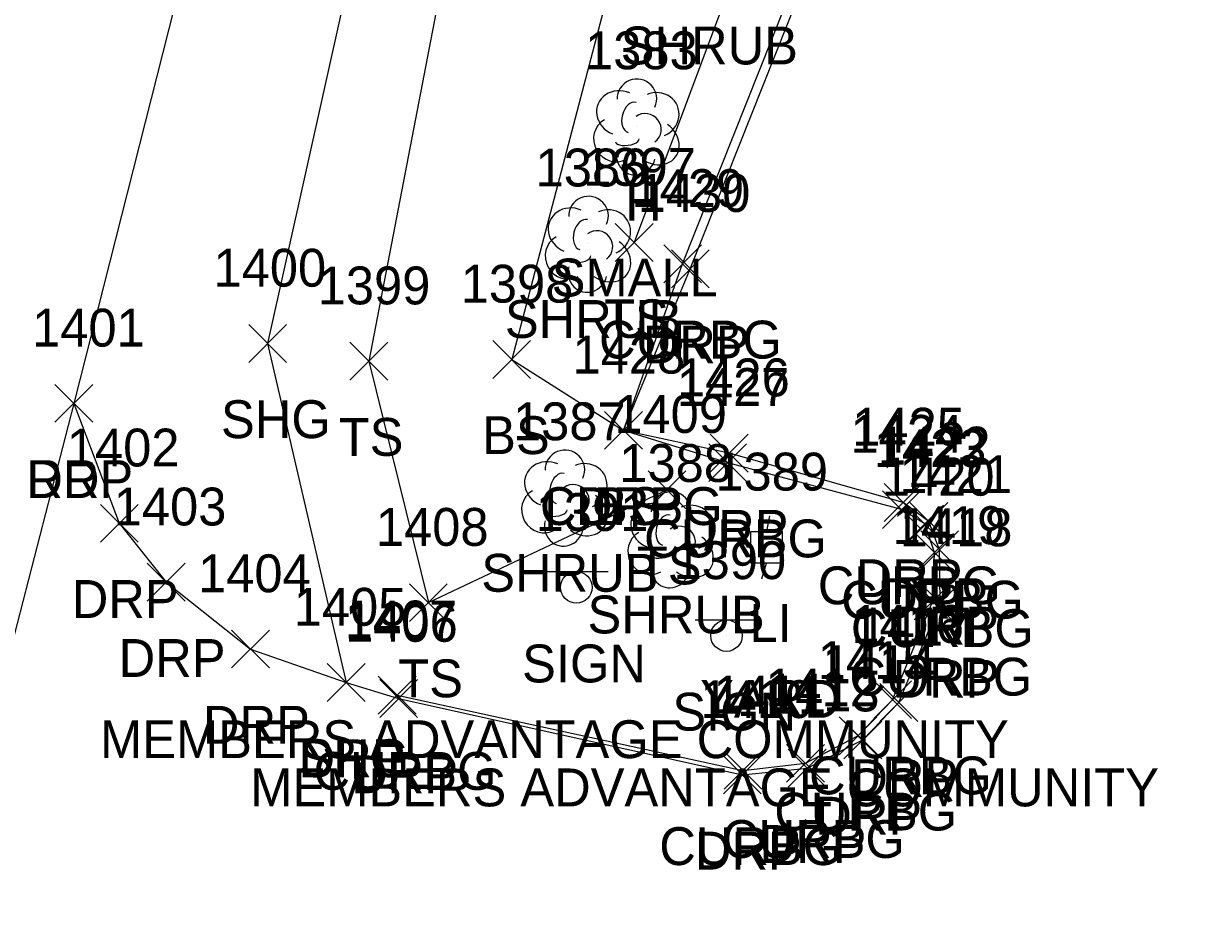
# Model space of a CAD drawing. Extents: x 1678863 to 1683592, y 407783 to 418211.
# Drawn here: x 1681308.9 to 1681370.7, y 417416.4 to 417462.9 of the extents above; entities that cross this region are included whole.
import ezdxf

# ---------------------------------------------------------------- set-up
doc = ezdxf.new("R2010")
doc.units = 0
for name, color, linetype in [('L_A', 7, 'Continuous'), ('L_C', 7, 'Continuous'), ('L_I', 7, 'Continuous'), ('L_TIC', 7, 'Continuous'), ('LELB', 7, 'Continuous'), ('LSH', 7, 'Continuous'), ('LTD', 7, 'Continuous'), ('P_A', 7, 'Continuous'), ('P_I', 7, 'Continuous'), ('P_TIC', 7, 'Continuous'), ('PET', 7, 'Continuous'), ('PSU', 7, 'Continuous'), ('R_A', 7, 'Continuous'), ('R_I', 7, 'Continuous'), ('R_TIC', 7, 'Continuous'), ('RC', 7, 'Continuous'), ('RDP', 7, 'Continuous'), ('S_A', 7, 'Continuous'), ('S_C', 7, 'Continuous'), ('S_I', 7, 'Continuous'), ('SSGN', 7, 'Continuous'), ('U_A', 7, 'Continuous'), ('U_C', 7, 'Continuous'), ('U_I', 7, 'Continuous'), ('ULP', 7, 'Continuous')]:
    doc.layers.add(name, color=color, linetype=linetype)

msp = doc.modelspace()

# ---------------------------------------------------------------- linework, layer by layer
at = {"layer": 'L_TIC'}
for points in [[(1681340.17, 417450.357), (1681342.17, 417452.357)], [(1681342.17, 417450.357), (1681340.17, 417452.357)], [(1681333.698, 417444.185), (1681335.698, 417446.185)], [(1681335.698, 417444.185), (1681333.698, 417446.185)], [(1681326.155, 417444.093), (1681328.155, 417446.093)], [(1681328.155, 417444.093), (1681326.155, 417446.093)], [(1681339.605, 417440.438), (1681341.605, 417442.438)], [(1681341.605, 417440.438), (1681339.605, 417442.438)], [(1681341.899, 417437.303), (1681343.899, 417439.303)], [(1681343.899, 417437.303), (1681341.899, 417439.303)], [(1681329.299, 417431.34), (1681331.299, 417433.34)], [(1681331.299, 417431.34), (1681329.299, 417433.34)]]:
    msp.add_lwpolyline(points, dxfattribs=at)
at = {"layer": 'LELB'}
for points in [[(1681470.09, 417678.472), (1681464.397, 417670.039), (1681442.503, 417656.839), (1681418.801, 417638.282), (1681396.246, 417609.841), (1681377.639, 417585.675), (1681362.846, 417559.022), (1681354.87, 417537.534), (1681350.306, 417518.503), (1681333.785, 417479.581), (1681327.155, 417445.093), (1681330.299, 417432.34), (1681342.899, 417438.303)], [(1681514.137, 417629.126), (1681463.152, 417652.962), (1681462.434, 417651.369), (1681461.205, 417645.122), (1681440.968, 417634.666), (1681416.613, 417613.365), (1681401.881, 417596.992), (1681391.042, 417583.905), (1681379.086, 417569.896), (1681365.417, 417533.875), (1681357.505, 417515.134), (1681342.597, 417475.248), (1681334.698, 417445.185), (1681340.605, 417441.438)], [(1681391.873, 417514.144), (1681366.763, 417524.314), (1681362.71, 417506.514), (1681348.973, 417472.236), (1681341.17, 417451.357)]]:
    msp.add_lwpolyline(points, dxfattribs=at)
at = {"layer": 'LSH'}
for p, q in [((1681338.71, 417451.32), (1681338.71, 417451.32)), ((1681338.71, 417451.32), (1681338.71, 417451.32)), ((1681337.462, 417437.915), (1681337.462, 417437.915)), ((1681337.462, 417437.915), (1681337.462, 417437.915)), ((1681343.074, 417435.714), (1681343.074, 417435.714)), ((1681343.074, 417435.714), (1681343.074, 417435.714))]:
    msp.add_line(p, q, dxfattribs=at)
for centre in [(1681338.757, 417452.754), (1681337.509, 417439.349), (1681343.121, 417437.148)]:
    msp.add_arc(centre, 1.047, 335.52715, 180.95627, dxfattribs=at)
for centre, major_axis, ratio, start_param, end_param in [((1681337.918, 417451.986), (1.21, -0.512), 0.895232, 1.570796, 4.712389), ((1681339.751, 417451.903), (-1.141, -0.483), 0.949671, 1.570796, 4.712389), ((1681338.501, 417451.778), (-0.208, -0.792), 0.645439, 3.141593, 6.283185), ((1681339.21, 417451.153), (-0.5, 0.667), 0.989748, 3.141593, 6.283185), ((1681337.627, 417450.611), (0.584, -1.042), 0.959034, 3.141593, 6.283185), ((1681339.71, 417450.487), (-1.09, 0.792), 0.841452, 1.570796, 4.712389), ((1681338.252, 417450.57), (-0.625, -0.083), 0.423636, 0, 3.141593), ((1681338.71, 417449.82), (0.265, 1.061), 0.942809, 1.570796, 4.712389), ((1681336.671, 417438.581), (1.21, -0.512), 0.895232, 1.570796, 4.712389), ((1681338.504, 417438.498), (-1.141, -0.483), 0.949671, 1.570796, 4.712389), ((1681337.254, 417438.373), (-0.208, -0.792), 0.645439, 3.141593, 6.283185), ((1681336.379, 417437.206), (0.584, -1.042), 0.959034, 3.141593, 6.283185), ((1681337.962, 417437.748), (-0.5, 0.667), 0.989748, 3.141593, 6.283185), ((1681338.463, 417437.082), (-1.09, 0.792), 0.841452, 1.570796, 4.712389), ((1681342.283, 417436.381), (1.21, -0.512), 0.895232, 1.570796, 4.712389), ((1681344.116, 417436.298), (-1.141, -0.483), 0.949671, 1.570796, 4.712389), ((1681337.004, 417437.165), (-0.625, -0.083), 0.423636, 0, 3.141593), ((1681342.866, 417436.173), (-0.208, -0.792), 0.645439, 3.141593, 6.283185), ((1681337.463, 417436.415), (0.265, 1.061), 0.942809, 1.570796, 4.712389), ((1681343.575, 417435.548), (-0.5, 0.667), 0.989748, 3.141593, 6.283185), ((1681341.991, 417435.006), (0.584, -1.042), 0.959034, 3.141593, 6.283185), ((1681344.075, 417434.881), (-1.09, 0.792), 0.841452, 1.570796, 4.712389), ((1681342.616, 417434.964), (-0.625, -0.083), 0.423636, 0, 3.141593), ((1681343.075, 417434.214), (0.265, 1.061), 0.942809, 1.570796, 4.712389)]:
    msp.add_ellipse(centre, major_axis=major_axis, ratio=ratio, start_param=start_param, end_param=end_param, dxfattribs=at)
at = {"layer": 'LTD'}
msp.add_line((1681341.266, 417457.51), (1681341.266, 417457.51), dxfattribs=at)
msp.add_line((1681341.266, 417457.51), (1681341.266, 417457.51), dxfattribs=at)
msp.add_arc((1681341.312, 417458.944), 1.047, 335.52715, 180.95627, dxfattribs=at)
for centre, major_axis, ratio, start_param, end_param in [((1681340.474, 417458.176), (1.21, -0.512), 0.895232, 1.570796, 4.712389), ((1681342.307, 417458.093), (-1.141, -0.483), 0.949671, 1.570796, 4.712389), ((1681341.057, 417457.968), (-0.208, -0.792), 0.645439, 3.141593, 6.283185), ((1681341.766, 417457.343), (-0.5, 0.667), 0.989748, 3.141593, 6.283185), ((1681340.183, 417456.801), (0.584, -1.042), 0.959034, 3.141593, 6.283185), ((1681342.266, 417456.677), (-1.09, 0.792), 0.841452, 1.570796, 4.712389), ((1681340.808, 417456.76), (-0.625, -0.083), 0.423636, 0, 3.141593), ((1681341.266, 417456.01), (0.265, 1.061), 0.942809, 1.570796, 4.712389)]:
    msp.add_ellipse(centre, major_axis=major_axis, ratio=ratio, start_param=start_param, end_param=end_param, dxfattribs=at)
at = {"layer": 'P_TIC'}
for points in [[(1681320.809, 417445.028), (1681322.809, 417447.028)], [(1681322.809, 417445.028), (1681320.809, 417447.028)], [(1681310.576, 417441.863), (1681312.576, 417443.863)], [(1681312.576, 417441.863), (1681310.576, 417443.863)], [(1681324.959, 417427.121), (1681326.959, 417429.121)], [(1681326.959, 417427.121), (1681324.959, 417429.121)]]:
    msp.add_lwpolyline(points, dxfattribs=at)
at = {"layer": 'PET'}
msp.add_lwpolyline([(1681690.633, 417744.781), (1681670.871, 417745.331), (1681641.84, 417743.059), (1681615.237, 417740.755), (1681586.041, 417734.442), (1681571.71, 417731.873), (1681544.313, 417723.634), (1681517.233, 417711.83), (1681495.671, 417702.4), (1681484.336, 417696.036), (1681457.741, 417677.974), (1681437.331, 417662.923), (1681415.268, 417643.118), (1681390.031, 417616.286), (1681370.504, 417590.975), (1681353.635, 417562.947), (1681343.43, 417542.938), (1681335.685, 417524.627), (1681321.925, 417483.7), (1681311.576, 417442.863), (1681297.797, 417389.402), (1681289.825, 417351.735), (1681280.092, 417307.991)], dxfattribs=at)
at = {"layer": 'PSU'}
msp.add_lwpolyline([(1681392.763, 417612.392), (1681374.057, 417587.57), (1681359.923, 417560.366), (1681351.092, 417539.507), (1681344.774, 417521.345), (1681329.757, 417481.789), (1681321.809, 417446.028), (1681325.959, 417428.121)], dxfattribs=at)
at = {"layer": 'R_TIC'}
for points in [[(1681342.727, 417449.232), (1681344.727, 417451.232)], [(1681344.727, 417449.232), (1681342.727, 417451.232)], [(1681343.132, 417448.975), (1681345.132, 417450.975)], [(1681345.132, 417448.975), (1681343.132, 417450.975)], [(1681310.576, 417441.863), (1681312.576, 417443.863)], [(1681312.576, 417441.863), (1681310.576, 417443.863)], [(1681339.605, 417440.438), (1681341.605, 417442.438)], [(1681341.605, 417440.438), (1681339.605, 417442.438)], [(1681339.605, 417440.438), (1681341.605, 417442.438)], [(1681341.605, 417440.438), (1681339.605, 417442.438)], [(1681345.185, 417439.236), (1681347.185, 417441.236)], [(1681347.185, 417439.236), (1681345.185, 417441.236)], [(1681345.106, 417438.731), (1681347.106, 417440.731)], [(1681347.106, 417438.731), (1681345.106, 417440.731)], [(1681354.284, 417436.252), (1681356.284, 417438.252)], [(1681356.284, 417436.252), (1681354.284, 417438.252)], [(1681354.379, 417436.631), (1681356.379, 417438.631)], [(1681356.379, 417436.631), (1681354.379, 417438.631)], [(1681312.976, 417435.531), (1681314.976, 417437.531)], [(1681314.976, 417435.531), (1681312.976, 417437.531)], [(1681355.731, 417435.632), (1681357.731, 417437.632)], [(1681357.731, 417435.632), (1681355.731, 417437.632)], [(1681355.513, 417435.495), (1681357.513, 417437.495)], [(1681357.513, 417435.495), (1681355.513, 417437.495)], [(1681356.028, 417433.989), (1681358.028, 417435.989)], [(1681358.028, 417433.989), (1681356.028, 417435.989)], [(1681356.301, 417434.125), (1681358.301, 417436.125)], [(1681358.301, 417434.125), (1681356.301, 417436.125)], [(1681315.452, 417432.416), (1681317.452, 417434.416)], [(1681317.452, 417432.416), (1681315.452, 417434.416)], [(1681355.95, 417431.43), (1681357.95, 417433.43)], [(1681357.95, 417431.43), (1681355.95, 417433.43)], [(1681356.321, 417431.316), (1681358.321, 417433.316)], [(1681358.321, 417431.316), (1681356.321, 417433.316)], [(1681319.905, 417428.889), (1681321.905, 417430.889)], [(1681321.905, 417428.889), (1681319.905, 417430.889)], [(1681324.959, 417427.121), (1681326.959, 417429.121)], [(1681326.959, 417427.121), (1681324.959, 417429.121)], [(1681327.651, 417426.45), (1681329.651, 417428.45)], [(1681329.651, 417426.45), (1681327.651, 417428.45)], [(1681327.729, 417426.273), (1681329.729, 417428.273)], [(1681329.729, 417426.273), (1681327.729, 417428.273)], [(1681353.819, 417426.213), (1681355.819, 417428.213)], [(1681355.819, 417426.213), (1681353.819, 417428.213)], [(1681354.148, 417426.07), (1681356.148, 417428.07)], [(1681356.148, 417426.07), (1681354.148, 417428.07)], [(1681351.986, 417424.305), (1681353.986, 417426.305)], [(1681353.986, 417424.305), (1681351.986, 417426.305)], [(1681352.244, 417424.086), (1681354.244, 417426.086)], [(1681354.244, 417424.086), (1681352.244, 417426.086)], [(1681349.22, 417422.855), (1681351.22, 417424.855)], [(1681351.22, 417422.855), (1681349.22, 417424.855)], [(1681349.302, 417422.595), (1681351.302, 417424.595)], [(1681351.302, 417422.595), (1681349.302, 417424.595)], [(1681345.882, 417422.243), (1681347.882, 417424.243)], [(1681347.882, 417422.243), (1681345.882, 417424.243)], [(1681345.912, 417422.48), (1681347.912, 417424.48)], [(1681347.912, 417422.48), (1681345.912, 417424.48)]]:
    msp.add_lwpolyline(points, dxfattribs=at)
at = {"layer": 'RC'}
msp.add_lwpolyline([(1681328.651, 417427.45), (1681346.912, 417423.48), (1681350.22, 417423.855), (1681352.986, 417425.305), (1681354.819, 417427.213), (1681356.95, 417432.43), (1681357.028, 417434.989), (1681356.513, 417436.495), (1681355.284, 417437.252), (1681346.106, 417439.731), (1681340.605, 417441.438), (1681343.727, 417450.232), (1681357.241, 417484.225), (1681365.508, 417505.086), (1681382.801, 417497.78), (1681385.891, 417504.714), (1681387.503, 417507.855), (1681389.053, 417509.619), (1681392.427, 417512.189), (1681395.029, 417513.729), (1681399.665, 417515.355)], dxfattribs=at)
at = {"layer": 'RDP'}
msp.add_lwpolyline([(1681311.576, 417442.863), (1681313.976, 417436.531), (1681316.452, 417433.416), (1681320.905, 417429.889), (1681325.959, 417428.121), (1681328.729, 417427.273), (1681346.882, 417423.243), (1681350.302, 417423.595), (1681353.244, 417425.086), (1681355.148, 417427.07), (1681357.321, 417432.316), (1681357.301, 417435.125), (1681356.731, 417436.632), (1681355.379, 417437.631), (1681346.185, 417440.236), (1681340.605, 417441.438), (1681344.132, 417449.975), (1681357.695, 417484.113), (1681365.7, 417504.488), (1681383.054, 417497.219)], dxfattribs=at)
at = {"layer": 'SSGN'}
for p, q in [((1681336.465, 417433.98), (1681339.799, 417433.98)), ((1681338.112, 417433.146), (1681338.112, 417433.146)), ((1681344.397, 417431.434), (1681347.731, 417431.434)), ((1681346.044, 417430.601), (1681346.044, 417430.601))]:
    msp.add_line(p, q, dxfattribs=at)
for centre in [(1681338.112, 417433.146), (1681346.044, 417430.601)]:
    msp.add_circle(centre, 0.833, dxfattribs=at)
at = {"layer": 'ULP'}
for p, q in [((1681348.322, 417436.928), (1681348.155, 417436.095)), ((1681347.322, 417434.428), (1681347.322, 417436.095)), ((1681347.322, 417436.095), (1681348.989, 417436.095)), ((1681348.989, 417436.095), (1681348.989, 417434.428)), ((1681348.155, 417435.261), (1681348.155, 417435.261)), ((1681348.989, 417434.428), (1681347.322, 417434.428)), ((1681347.905, 417433.595), (1681348.155, 417434.428))]:
    msp.add_line(p, q, dxfattribs=at)

# ---------------------------------------------------------------- texts
at = {"layer": 'L_A'}
for s, p in [('SHRUB', (1681340.456, 417460.766)), ('H', (1681340.699, 417452.51)), ('SHRUB', (1681334.34, 417446.32)), ('TS', (1681339.58, 417446.357)), ('TS', (1681325.564, 417440.093)), ('BS', (1681333.139, 417440.185)), ('BS', (1681339.046, 417436.438)), ('TS', (1681341.308, 417433.303)), ('SHRUB', (1681333.092, 417432.915)), ('SHRUB', (1681338.704, 417430.714)), ('TS', (1681328.709, 417427.34))]:
    msp.add_text(s, height=2, dxfattribs=at).set_placement(p)
at = {"layer": 'L_C'}
msp.add_text('SMALL', height=2, dxfattribs=at).set_placement((1681336.809, 417448.51))
at = {"layer": 'L_I'}
for s, p in [('1383', (1681338.573, 417460.51)), ('1386', (1681335.962, 417454.32)), ('1397', (1681338.477, 417454.357)), ('1399', (1681324.454, 417448.093)), ('1398', (1681332.005, 417448.185)), ('1428', (1681337.912, 417444.438)), ('1409', (1681340.119, 417441.303)), ('1387', (1681334.769, 417440.915)), ('1388', (1681340.382, 417438.714)), ('1408', (1681327.527, 417435.34))]:
    msp.add_text(s, height=2, dxfattribs=at).set_placement(p)
at = {"layer": 'P_A'}
for s, p in [('SHG', (1681319.345, 417441.028)), ('RDP', (1681309.064, 417437.863)), ('SHG', (1681323.494, 417423.121))]:
    msp.add_text(s, height=2, dxfattribs=at).set_placement(p)
at = {"layer": 'P_I'}
for s, p in [('1400', (1681318.951, 417449.028)), ('1401', (1681309.371, 417445.863)), ('1405', (1681323.187, 417431.121))]:
    msp.add_text(s, height=2, dxfattribs=at).set_placement(p)
at = {"layer": 'R_A'}
for s, p in [('CURBG', (1681339.31, 417445.232)), ('DRP', (1681341.621, 417444.975)), ('DRP', (1681309.064, 417437.863)), ('CURBG', (1681336.187, 417436.438)), ('DRP', (1681338.093, 417436.438)), ('DRP', (1681343.673, 417435.236)), ('CURBG', (1681341.689, 417434.731)), ('DRP', (1681352.867, 417432.631)), ('CURBG', (1681350.867, 417432.252)), ('DRP', (1681311.464, 417431.531)), ('CURBG', (1681352.095, 417431.495)), ('DRP', (1681354.219, 417431.632)), ('CURBG', (1681352.611, 417429.989)), ('DRP', (1681354.789, 417430.125)), ('DRP', (1681313.94, 417428.416)), ('CURBG', (1681352.533, 417427.43)), ('DRP', (1681354.81, 417427.316)), ('DRP', (1681318.394, 417424.889)), ('DRP', (1681323.447, 417423.121)), ('CURBG', (1681324.234, 417422.45)), ('DRP', (1681326.218, 417422.273)), ('CURBG', (1681350.402, 417422.213)), ('DRP', (1681352.636, 417422.07)), ('CURBG', (1681348.569, 417420.305)), ('DRP', (1681350.733, 417420.086)), ('CURBG', (1681345.803, 417418.855)), ('CURBG', (1681342.495, 417418.48)), ('DRP', (1681344.37, 417418.243)), ('DRP', (1681347.79, 417418.595))]:
    msp.add_text(s, height=2, dxfattribs=at).set_placement(p)
at = {"layer": 'R_I'}
for s, p in [('1429', (1681341.026, 417453.232)), ('1430', (1681341.353, 417452.975)), ('1401', (1681309.371, 417445.863)), ('1428', (1681337.912, 417444.438)), ('1428', (1681337.912, 417444.438)), ('1426', (1681343.437, 417443.236)), ('1427', (1681343.413, 417442.731)), ('1425', (1681352.686, 417440.631)), ('1424', (1681352.592, 417440.252)), ('1402', (1681311.204, 417439.531)), ('1423', (1681353.82, 417439.495)), ('1422', (1681354.038, 417439.632)), ('1420', (1681354.249, 417437.989)), ('1421', (1681355.175, 417438.125)), ('1403', (1681313.68, 417436.416)), ('1419', (1681354.816, 417435.43)), ('1418', (1681355.195, 417435.316)), ('1404', (1681318.134, 417432.889)), ('1405', (1681323.187, 417431.121)), ('1407', (1681325.88, 417430.45)), ('1406', (1681325.903, 417430.273)), ('1416', (1681352.638, 417430.213)), ('1417', (1681353.022, 417430.07)), ('1415', (1681350.86, 417428.305)), ('1414', (1681351.118, 417428.086)), ('1412', (1681348.094, 417426.855)), ('1410', (1681344.669, 417426.243)), ('1411', (1681345.353, 417426.48)), ('1413', (1681348.176, 417426.595))]:
    msp.add_text(s, height=2, dxfattribs=at).set_placement(p)
at = {"layer": 'S_A'}
for p in [(1681335.25, 417428.126), (1681343.182, 417425.581)]:
    msp.add_text('SIGN', height=2, dxfattribs=at).set_placement(p)
at = {"layer": 'S_C'}
for p in [(1681312.959, 417424.126), (1681320.891, 417421.581)]:
    msp.add_text('MEMBERS ADVANTAGE COMMUNITY', height=2, dxfattribs=at).set_placement(p)
at = {"layer": 'S_I'}
for s, p in [('1391', (1681335.967, 417436.126)), ('1390', (1681343.245, 417433.581))]:
    msp.add_text(s, height=2, dxfattribs=at).set_placement(p)
at = {"layer": 'U_A'}
msp.add_text('LI', height=2, dxfattribs=at).set_placement((1681347.258, 417430.261))
at = {"layer": 'U_C'}
msp.add_text('YARD', height=2, dxfattribs=at).set_placement((1681344.651, 417426.261))
at = {"layer": 'U_I'}
msp.add_text('1389', height=2, dxfattribs=at).set_placement((1681345.455, 417438.261))

doc.saveas('drawing.dxf')
